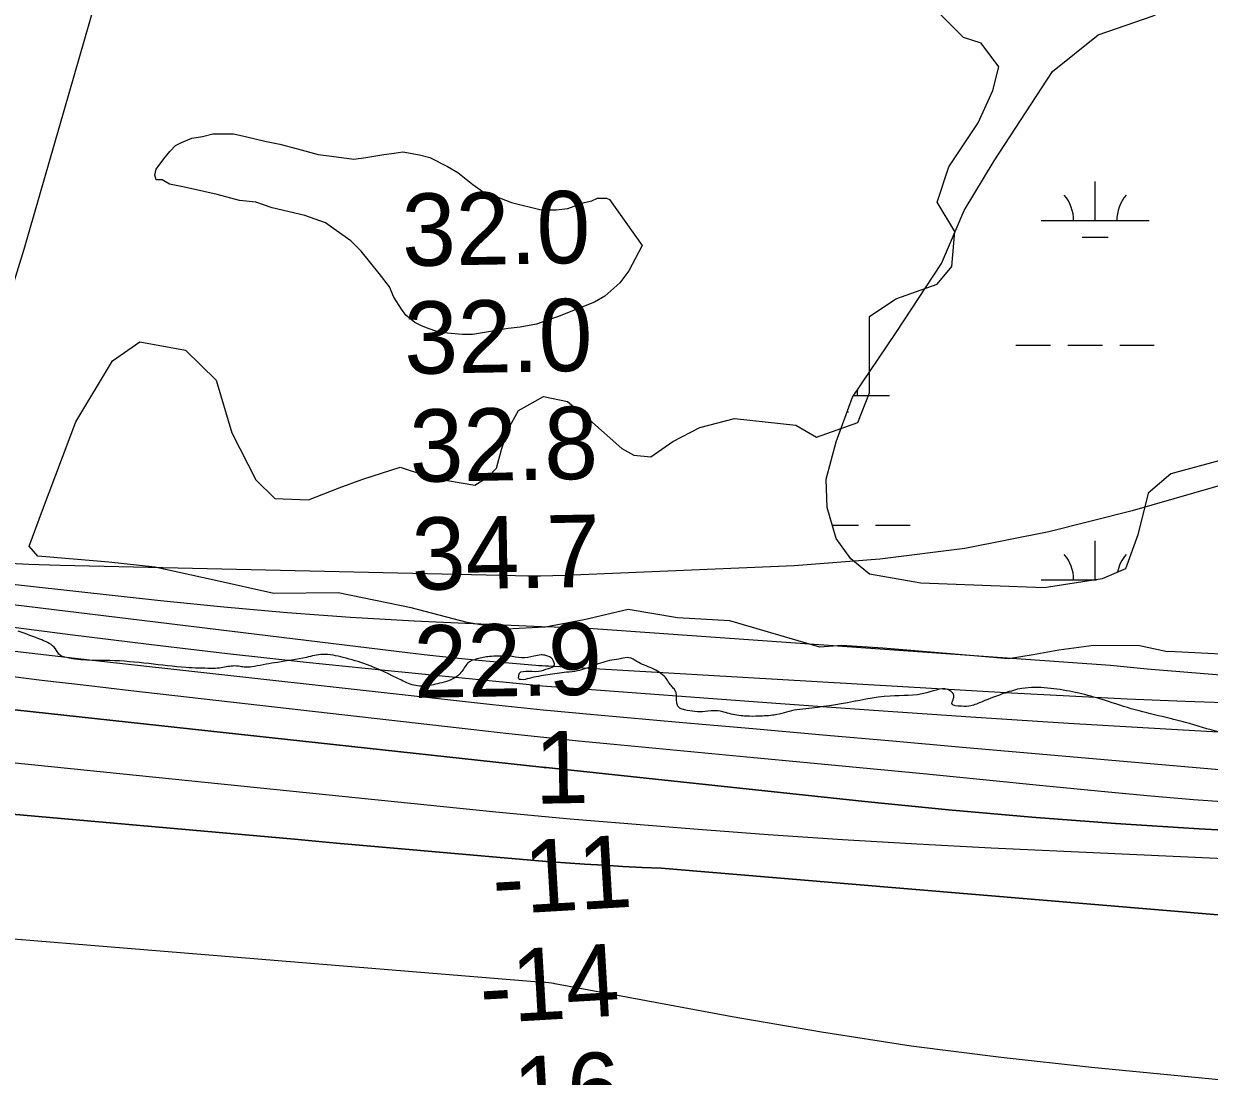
# Model space of a CAD drawing. Extents: x 3297772 to 3335630, y 634068 to 659439.
# Drawn here: x 3325224 to 3326321, y 647396 to 648371 of the extents above; entities that cross this region are included whole.
import ezdxf

# ---------------------------------------------------------------- set-up
doc = ezdxf.new("R2010")
doc.units = 0
for name, color, linetype in [('V-RIVR-EDGE', 7, 'Continuous'), ('V-RIVR-RANG', 7, 'Continuous'), ('V-SITE-VEGE', 7, 'Continuous'), ('V-TOPO-DPTH', 7, 'Continuous'), ('V-TOPO-MAJR', 7, 'Continuous'), ('V-TOPO-MINR', 7, 'Continuous'), ('V-TOPO-WATR', 7, 'Continuous'), ('V-WETL-SWMP', 7, 'Continuous')]:
    doc.layers.add(name, color=color, linetype=linetype)

msp = doc.modelspace()

# ---------------------------------------------------------------- linework, layer by layer
at = {"layer": 'V-RIVR-EDGE'}
for points in [[(3333439.4, 648130.1), (3333432.3, 648128.6), (3333393.5, 648121.3), (3333365.9, 648117.1), (3333332.2, 648114.9), (3333298.4, 648114.2), (3333260.8, 648112.7), (3333230.2, 648112), (3333195.3, 648109), (3333136.3, 648103), (3333088.6, 648097.7), (3333047.1, 648092.7), (3333001.7, 648085.1), (3332967.9, 648078.9), (3332933.4, 648077.1), (3332910.9, 648076), (3332895, 648074.5), (3332874.5, 648073.4), (3332860.9, 648070.3), (3332849.2, 648064.9), (3332842.2, 648063), (3332807, 648061.9), (3332785.2, 648058.1), (3332742.9, 648051.2), (3332702.2, 648046.3), (3332606, 648034.5), (3332570.7, 648028.4), (3332514.8, 648018.8), (3332458.6, 648008.9), (3332396.1, 648000.5), (3332317.7, 647987.9), (3332285.5, 647982.5), (3332246.4, 647976.4), (3332208, 647971.9), (3332152.9, 647965.8), (3332088.5, 647961.3), (3332048.9, 647954.8), (3332019, 647950.2), (3331983.4, 647943.3), (3331945.3, 647935.7), (3331898, 647927.6), (3331843.3, 647918.1), (3331789, 647907.7), (3331738.2, 647900.5), (3331714.1, 647898.6), (3331693.9, 647894), (3331644.7, 647886.8), (3331609.4, 647880.3), (3331580.3, 647876.1), (3331563.2, 647876.1), (3331548.1, 647876.5), (3331538.4, 647876.2), (3331524.8, 647873.9), (3331503.5, 647868.5), (3331463.9, 647860.5), (3331403, 647851.3), (3331393.3, 647846.7), (3331382, 647841.3), (3331348.6, 647836.3), (3331302.5, 647830.2), (3331254.8, 647825.7), (3331162.1, 647821.6), (3331119, 647820.6), (3331084.5, 647817.2), (3331048, 647811.1), (3330992.9, 647804.6), (3330947.6, 647800.1), (3330916.9, 647796.7), (3330882, 647795.2), (3330846.7, 647791.4), (3330781.9, 647785.7), (3330745.1, 647780), (3330721.8, 647780.1), (3330687.3, 647783.7), (3330659, 647784.9), (3330629.5, 647784.6), (3330565.1, 647780.1), (3330512.8, 647775.2), (3330464.3, 647771.4), (3330411.1, 647764.9), (3330328.9, 647756.6), (3330280.8, 647752.5), (3330223, 647743.7), (3330159.8, 647733.8), (3330098.9, 647726.2), (3330018.6, 647717.1), (3329963.9, 647709.4), (3329917.7, 647703), (3329903.4, 647702.2), (3329890.6, 647702.2), (3329873.5, 647706.9), (3329862.3, 647707.7), (3329851.8, 647705.8), (3329827.7, 647698.9), (3329814.5, 647697.4), (3329809.5, 647696.6), (3329807.9, 647698.6), (3329806.8, 647701.7), (3329801.8, 647702.1), (3329782.7, 647701.3), (3329745.5, 647698.7), (3329718.7, 647695.7), (3329678, 647692.7), (3329648.1, 647688.9), (3329602, 647682), (3329556.2, 647675.9), (3329520.9, 647674.5), (3329508.1, 647675.3), (3329497.3, 647678.4), (3329465.5, 647674.6), (3329435.2, 647672.7), (3329406.1, 647671.3), (3329386.7, 647673.2), (3329372, 647678.7), (3329360.8, 647680.7), (3329347.6, 647681.5), (3329329.4, 647681.1), (3329318.9, 647676.5), (3329310, 647675.4), (3329285.5, 647674.7), (3329264.2, 647671.2), (3329230, 647669), (3329205.6, 647671), (3329192.8, 647669.5), (3329173.8, 647668.3), (3329159.9, 647669.5), (3329154.8, 647672.7), (3329142, 647670), (3329119.5, 647667.3), (3329104.4, 647666.2), (3329092.4, 647665.1), (3329070.3, 647665.1), (3329052.4, 647664.4), (3329042.7, 647664.8), (3329037.3, 647667.1), (3329035.4, 647670.6), (3329031.1, 647673), (3329023.4, 647673.4), (3329005.9, 647675.3), (3328975.7, 647679.3), (3328944.7, 647682.1), (3328895.4, 647682.6), (3328867.5, 647686.5), (3328838.8, 647688.6), (3328809.3, 647690.2), (3328773.7, 647691.8), (3328729.1, 647689.6), (3328666.2, 647693.6), (3328624.8, 647694.9), (3328580.2, 647695.8), (3328546.8, 647693.5), (3328506.8, 647687.1), (3328492.9, 647683.2), (3328482.8, 647675.1), (3328471.9, 647673.2), (3328434.3, 647669.8), (3328399.4, 647666.8), (3328372.6, 647660.6), (3328345.8, 647656.4), (3328313.2, 647653.4), (3328276, 647651.6), (3328220.2, 647646.3), (3328210.4, 647641.6), (3328198, 647638.2), (3328173.6, 647636.7), (3328112.7, 647631.8), (3328044, 647626.5), (3328041.3, 647628.5), (3328031.7, 647644), (3328021.2, 647654.5), (3328011.2, 647660.4), (3327998, 647665.8), (3327984.4, 647669), (3327951.1, 647672.1), (3327903.4, 647675), (3327857.3, 647678.6), (3327817.7, 647677.9), (3327782.8, 647676.4), (3327750.6, 647676.1), (3327707.9, 647675.5), (3327667.6, 647675.6), (3327640.5, 647680.3), (3327623.8, 647683), (3327599.4, 647684.3), (3327563.3, 647682), (3327529.2, 647680.2), (3327489.2, 647675.2), (3327442.7, 647667.6), (3327414.7, 647665.7), (3327389.5, 647666.2), (3327373.6, 647665.4), (3327367.4, 647667.4), (3327351.5, 647674.4), (3327334.1, 647680.3), (3327331.8, 647683.8), (3327330.3, 647688.8), (3327320.6, 647691.9), (3327317.5, 647695.8), (3327317.9, 647700.9), (3327315.2, 647702.8), (3327303.2, 647707.1), (3327298.5, 647707.5), (3327292.3, 647704.8), (3327281.8, 647701.7), (3327271.7, 647701.7), (3327235.3, 647702.2), (3327199.2, 647703.5), (3327169, 647704.3), (3327108.9, 647708.3), (3327072.8, 647712.7), (3327031.7, 647717.5), (3326986.7, 647719.9), (3326955.3, 647719.2), (3326928.9, 647718.1), (3326908, 647716.2), (3326887.8, 647708.1), (3326876.2, 647702.7), (3326868.8, 647702), (3326856.8, 647704.7), (3326842, 647704.7), (3326809.5, 647703.3), (3326777.3, 647698.3), (3326760.2, 647695.6), (3326748.9, 647691.4), (3326738.1, 647689.5), (3326737.3, 647691), (3326736.9, 647694.9), (3326734.6, 647696.9), (3326712.9, 647700.4), (3326678.4, 647702), (3326660.2, 647703.6), (3326628.4, 647711.5), (3326607.8, 647715.4), (3326582.6, 647714.3), (3326557, 647710.1), (3326535.7, 647709), (3326505.8, 647710.2), (3326476, 647711.9), (3326436.8, 647712.7), (3326394.5, 647711.7), (3326361.6, 647711.7), (3326334.8, 647714.1), (3326302.7, 647722.8), (3326245.3, 647737.6), (3326217, 647746.6), (3326194.5, 647752.1), (3326171.3, 647755.7), (3326147.6, 647755.3), (3326132.1, 647751.1), (3326110.7, 647743), (3326100.3, 647739.2), (3326091.7, 647738.8), (3326082.8, 647741.5), (3326084.4, 647746.2), (3326084.4, 647749.7), (3326081.3, 647753.2), (3326059.6, 647751.3), (3326025.8, 647748.3), (3325980.4, 647741), (3325936.6, 647735.3)], [(3325936.6, 647735.3), (3325918.4, 647730.7), (3325904, 647729.6), (3325892.8, 647729.6), (3325878.4, 647731.6), (3325864.9, 647734.7), (3325854.4, 647733.9), (3325835.4, 647735.5), (3325831.1, 647737.1), (3325828.8, 647739.8), (3325828, 647743.7), (3325826.5, 647753.8), (3325823.8, 647756.9), (3325817.6, 647765.4), (3325805.2, 647774), (3325791.3, 647780.2), (3325783.9, 647783.8), (3325776.9, 647783), (3325768, 647781.5), (3325751.3, 647776.5), (3325736.2, 647771.5), (3325726.1, 647770.3), (3325708.7, 647768), (3325691.6, 647764.6), (3325683.8, 647763.5), (3325681.9, 647764.2), (3325681.9, 647766.6), (3325681.9, 647767.7), (3325700.1, 647771.2), (3325709.4, 647773.9), (3325714.9, 647776.9), (3325714.5, 647779.7), (3325713, 647782.4), (3325707.1, 647785.9), (3325702.5, 647786.3), (3325695.9, 647785.1), (3325684.6, 647783.6), (3325673, 647785.2), (3325662.9, 647785.2), (3325654.8, 647784.9), (3325643.2, 647782.6), (3325634.6, 647778.7), (3325631.5, 647774.4), (3325624.5, 647766.3), (3325608.6, 647760.1), (3325593.8, 647757.5), (3325586.5, 647757.9), (3325573.3, 647762.9), (3325541.1, 647777.4), (3325519.4, 647784), (3325500.5, 647786.8), (3325485.3, 647784.1), (3325458.6, 647779.5), (3325437.2, 647775.7), (3325429.1, 647774.9), (3325424, 647775.7), (3325417.4, 647776.1), (3325405, 647774.2), (3325396.9, 647773.9), (3325374, 647774.7), (3325339.5, 647778.3), (3325303.4, 647781.1), (3325260.4, 647784.7), (3325257.7, 647785.8), (3325253, 647792), (3325240.3, 647800.2), (3325218.6, 647808.4)]]:
    msp.add_spline(points, degree=3, dxfattribs=at)
at = {"layer": 'V-SITE-VEGE'}
for points in [[(3325326.3, 648517.3), (3325223.7, 648161.8), (3325142.4, 647899.2), (3325139.3, 647891.3), (3325126.8, 647883.4), (3325085.9, 647889.4), (3324990.2, 647891.8), (3324842.5, 647908), (3324762.4, 647920), (3324715.2, 647935.4), (3324671.2, 647950.8), (3324627.1, 647961.5), (3324584.7, 647969), (3324501.5, 647979.4), (3324405.8, 647970.9), (3324357.1, 647970.5), (3324299, 647982.7), (3324218.8, 648005.7)], [(3325804.2, 647969.8), (3325824.5, 647984), (3325849.5, 647996.8), (3325881.6, 648005.4), (3325938.5, 647999), (3325957.6, 647988.1), (3325995.6, 648001.7), (3326006.5, 648028.9), (3326006.5, 648056.1), (3326006.5, 648099.6), (3326031, 648116), (3326069.1, 648129.6), (3326082.7, 648145.9), (3326085.4, 648178.5), (3326069.1, 648205.7), (3326079.9, 648238.4), (3326107.1, 648279.2), (3326120.7, 648309.1), (3326126.2, 648330.9), (3326109.9, 648352.7), (3326093.5, 648358.1), (3326063.6, 648388)], [(3326331.8, 647787), (3326283.6, 647789.4), (3326282.3, 647789.1), (3326256.3, 647794.9), (3326214.2, 647795), (3326181.7, 647790.7), (3326158.1, 647786.5), (3326135.2, 647782.7), (3326085.3, 647787), (3326018.8, 647792.5), (3325980.9, 647795.2), (3325960.7, 647793.5), (3325877.4, 647818), (3325828.8, 647820.8), (3325783.2, 647828.4), (3325742.5, 647818.7), (3325706.4, 647812.1), (3325670.3, 647810.3), (3325634.2, 647816.3), (3325582.3, 647830.1), (3325514.7, 647843.7), (3325455.1, 647843.3), (3325400.1, 647855.5), (3325345, 647867.6), (3325302.6, 647872.1), (3325269.7, 647875), (3325236.7, 647877.9), (3325228.8, 647887.2), (3325241.1, 647920.3), (3325271.9, 648002.1), (3325306, 648058.8), (3325331, 648076.3), (3325373.4, 648068.7), (3325401.9, 648040.7), (3325416.4, 647992.1), (3325438.6, 647948.4), (3325456, 647931.2), (3325487.4, 647929.9), (3325515.6, 647941), (3325537.5, 647949), (3325572, 647960.3), (3325595.6, 647952.6), (3325616, 647948), (3325641.1, 647943.5), (3325653.6, 647951.4), (3325661.4, 647959.3), (3325666, 647976.6), (3325672.2, 647995.5), (3325681.5, 648012.8), (3325704.9, 648025.6), (3325726.9, 648021), (3325747.4, 648003.9), (3325777.4, 647977.4), (3325788.5, 647971.2), (3325804.2, 647969.8)]]:
    msp.add_lwpolyline(points, dxfattribs=at)
msp.add_lwpolyline([(3325796.1, 648165.4), (3325783.7, 648142), (3325775.4, 648131), (3325761.7, 648118.6), (3325752, 648113.1), (3325717.6, 648099.4), (3325709.4, 648096.7), (3325698.4, 648092.6), (3325683.2, 648089.8), (3325672.2, 648088.5), (3325639.2, 648083), (3325629.6, 648083), (3325615.8, 648084.4), (3325606.2, 648085.8), (3325597.9, 648088.6), (3325591.1, 648091.3), (3325585.6, 648094.1), (3325577.3, 648101), (3325573.2, 648106.5), (3325566.3, 648117.5), (3325562.2, 648127.1), (3325552.6, 648139.5), (3325536.1, 648160.2), (3325526.5, 648169.8), (3325512.8, 648179.5), (3325503.1, 648186.3), (3325483.9, 648193.2), (3325453.6, 648200.2), (3325438.5, 648205.7), (3325423.4, 648207.1), (3325402.7, 648212.6), (3325390.4, 648215.4), (3325372.5, 648219.5), (3325358.7, 648222.3), (3325351.9, 648226.4), (3325346.4, 648226.4), (3325345, 648230.5), (3325346.4, 648236), (3325353.3, 648245.7), (3325358.8, 648252.5), (3325364.3, 648258), (3325369.8, 648260.8), (3325379.4, 648264.9), (3325389.1, 648266.3), (3325398.7, 648269), (3325417.9, 648269), (3325430.3, 648266.2), (3325446.8, 648262.1), (3325460.6, 648259.3), (3325477.1, 648255.1), (3325496.3, 648249.6), (3325508.7, 648248.2), (3325529.3, 648245.5), (3325540.3, 648246.8), (3325556.9, 648249.6), (3325566.5, 648250.9), (3325574.7, 648252.3), (3325589.9, 648249.5), (3325599.5, 648246.8), (3325616, 648238.5), (3325625.6, 648233), (3325639.4, 648221.9), (3325649, 648215.1), (3325664.1, 648209.5), (3325675.1, 648205.4), (3325702.6, 648198.5), (3325716.4, 648198.5), (3325727.4, 648199.8), (3325742.5, 648205.3), (3325749.4, 648206.7), (3325754.9, 648209.4), (3325763.1, 648209.4), (3325765.9, 648208)], close=True, dxfattribs=at)
at = {"layer": 'V-TOPO-DPTH'}
for points in [[(3326436.5, 647670.6), (3326092.6, 647700.7), (3326027.9, 647706.4), (3325963.2, 647712.1), (3325898.5, 647717.8), (3325833.8, 647723.5), (3325751.3, 647730.8), (3325727.9, 647733), (3325704.4, 647735.2), (3325681, 647737.7), (3325657.6, 647740.2), (3325284.5, 647781.5), (3325249.9, 647785.4), (3325215.3, 647789.5)], [(3325113, 647746.6), (3325703.2, 647682.5), (3325703.5, 647682.4), (3325705.5, 647682.2), (3325706.4, 647682.1), (3325707, 647682.1), (3325707.3, 647682), (3326002.3, 647650.6), (3326079.6, 647642.9), (3326156.8, 647636.1), (3326234.2, 647630.4), (3326311.6, 647625.4), (3326413.7, 647619.7)], [(3325113, 647746.6), (3325703.2, 647682.5), (3325703.5, 647682.4), (3325705.5, 647682.2), (3325706.4, 647682.1), (3325707, 647682.1), (3325707.3, 647682), (3326002.3, 647650.6), (3326079.6, 647642.9), (3326156.8, 647636.1), (3326234.2, 647630.4), (3326311.6, 647625.4), (3326413.7, 647619.7)], [(3325104.7, 647648.6), (3325474.4, 647615.7), (3325513.2, 647612.2), (3325552, 647608.7), (3325590.8, 647605.3), (3325629.6, 647601.9), (3325671.8, 647598.2), (3325689.6, 647596.6), (3325707.3, 647595.2), (3325725, 647593.9), (3325742.7, 647592.7), (3325760.5, 647591.6), (3325778.2, 647590.5), (3325796, 647589.6), (3325813.8, 647588.8), (3326506.2, 647530.9)], [(3326506.2, 647530.9), (3325813.8, 647588.8), (3325796, 647589.6), (3325778.2, 647590.5), (3325760.5, 647591.6), (3325742.7, 647592.7), (3325725, 647593.9), (3325707.3, 647595.2), (3325689.6, 647596.6), (3325671.8, 647598.2), (3325629.6, 647601.9), (3325590.8, 647605.3), (3325552, 647608.7), (3325513.2, 647612.2), (3325474.4, 647615.7), (3325104.7, 647648.6)]]:
    msp.add_lwpolyline(points, dxfattribs=at)
at = {"layer": 'V-TOPO-MAJR'}
msp.add_lwpolyline([(3326331.5, 647767.7), (3326297.5, 647770.4), (3326263.5, 647773.3), (3326229.5, 647776.6), (3325737.9, 647811.6), (3325702.8, 647812.5), (3325667.8, 647813.8), (3325632.7, 647815.4), (3325585.1, 647817.7), (3325526.3, 647821.1), (3325467.5, 647825.3), (3325408.9, 647830.5), (3325350.2, 647836.4), (3325106.5, 647863.2)], dxfattribs=at)
at = {"layer": 'V-TOPO-MINR'}
for points in [[(3326363.2, 647952.5), (3326249.8, 647919.7), (3326172.6, 647900.4), (3326094.8, 647884.8), (3326016, 647874.9), (3325936.7, 647868.8), (3325724.9, 647860), (3325713.4, 647859.6), (3325701.9, 647859.4), (3325690.3, 647859.4), (3325678.8, 647859.6), (3325257.4, 647869.2), (3325228.3, 647870.2), (3325199.1, 647871.7)], [(3326352.4, 647741.4), (3326298.8, 647743.3), (3326245.1, 647745.5), (3326191.5, 647748.1), (3326137.9, 647751), (3325709.5, 647775.8), (3325706.5, 647776), (3325703.6, 647776.2), (3325700.6, 647776.4), (3325697.6, 647776.6), (3325662, 647779.7), (3325641.2, 647781.6), (3325620.4, 647783.6), (3325599.7, 647785.9), (3325578.9, 647788.3), (3325122.2, 647843.8)], [(3326399.4, 647710.9), (3326280.9, 647717.7), (3326190.6, 647723), (3326100.4, 647728.7), (3326010.1, 647734.9), (3325919.9, 647741.3), (3325728.6, 647755.6), (3325716.3, 647756.5), (3325704, 647757.5), (3325691.7, 647758.6), (3325679.4, 647759.8), (3325558, 647771.8), (3325485.1, 647779.4), (3325412.2, 647787.4), (3325339.4, 647796), (3325266.7, 647805), (3325140.1, 647821.3)], [(3326436.5, 647670.6), (3326092.6, 647700.7), (3326027.9, 647706.4), (3325963.2, 647712.1), (3325898.5, 647717.8), (3325833.8, 647723.5), (3325751.3, 647730.8), (3325727.9, 647733), (3325704.4, 647735.2), (3325681, 647737.7), (3325657.6, 647740.2), (3325284.5, 647781.5), (3325249.9, 647785.4), (3325215.3, 647789.5)], [(3326346.1, 647649.4), (3326306.5, 647652.3), (3326266.9, 647655.6), (3326227.3, 647659.3), (3326166.9, 647665.3), (3326111.6, 647670.8), (3326056.2, 647676.2), (3326000.8, 647681.5), (3325945.4, 647686.7), (3325899.4, 647691), (3325867, 647694.1), (3325834.6, 647697.1), (3325802.2, 647700.2), (3325769.8, 647703.3), (3325737.3, 647706.5), (3325705, 647709.8), (3325672.6, 647713.3), (3325640.2, 647716.9), (3325322.8, 647753.2), (3325281.6, 647758), (3325240.3, 647762.8), (3325199.1, 647767.8)], [(3326422.5, 647593.6), (3326119.2, 647607.5), (3326050.3, 647611), (3325981.5, 647615), (3325912.7, 647619.8), (3325843.9, 647625), (3325752.3, 647632.4), (3325729.4, 647634.3), (3325706.4, 647636.4), (3325683.5, 647638.5), (3325660.7, 647640.8), (3325234.1, 647684.2), (3325206.6, 647687.1)], [(3326506.2, 647530.9), (3325813.8, 647588.8), (3325796, 647589.6), (3325778.2, 647590.5), (3325760.5, 647591.6), (3325742.7, 647592.7), (3325725, 647593.9), (3325707.3, 647595.2), (3325689.6, 647596.6), (3325671.8, 647598.2), (3325629.6, 647601.9), (3325590.8, 647605.3), (3325552, 647608.7), (3325513.2, 647612.2), (3325474.4, 647615.7), (3325104.7, 647648.6)], [(3326460.9, 647380.2), (3326211.9, 647404.3), (3326128.4, 647413.5), (3326045.2, 647424.1), (3325962.2, 647437), (3325879.5, 647451.3), (3325715.4, 647481.9), (3325714.3, 647482.1), (3325712.1, 647482.4), (3325709.8, 647482.7), (3325706.5, 647483), (3325703.5, 647483.2), (3325700.4, 647483.4), (3325112.2, 647531.6)]]:
    msp.add_lwpolyline(points, dxfattribs=at)
at = {"layer": 'V-TOPO-WATR'}
msp.add_lwpolyline([(3326413.7, 647619.7), (3326311.6, 647625.4), (3326234.2, 647630.4), (3326156.8, 647636.1), (3326079.6, 647642.9), (3326002.3, 647650.6), (3325707.3, 647682), (3325707, 647682.1), (3325706.4, 647682.1), (3325705.5, 647682.2), (3325703.5, 647682.4), (3325703.2, 647682.5), (3325113, 647746.6)], dxfattribs=at)
at = {"layer": 'V-WETL-SWMP'}
for p, q in [((3326215.5, 648188.6), (3326215.5, 648224.6)), ((3326165.5, 648188.6), (3326265.5, 648188.6)), ((3326203.5, 648173.1), (3326227.5, 648173.1)), ((3326142.1, 648073.1), (3326174.1, 648073.1)), ((3326190.1, 648073.1), (3326222.1, 648073.1)), ((3326238.1, 648073.1), (3326270.1, 648073.1)), ((3325992.1, 648026.7), (3326025, 648026.7)), ((3325985.9, 648011.3), (3325987, 648011.3)), ((3325972, 647906.6), (3325996.2, 647906.6)), ((3326012.2, 647906.6), (3326044.2, 647906.6)), ((3326215.5, 647855.9), (3326215.5, 647891.9)), ((3326165.5, 647855.9), (3326216.6, 647855.9))]:
    msp.add_line(p, q, dxfattribs=at)
msp.add_lwpolyline([(3326341.3, 647969.1), (3326285.3, 647953.9), (3326264.4, 647936.2), (3326254.9, 647897.5), (3326243.4, 647866.1), (3326221.9, 647856.7), (3326168.1, 647848.4), (3326054, 647852.7), (3326006.4, 647861.2), (3325989.2, 647875.3), (3325975.6, 647894.2), (3325967.3, 647922.9), (3325966.3, 647949.1), (3325975.7, 647983.6), (3325990.9, 648024.9), (3326031.3, 648085), (3326073.2, 648148.8), (3326094.2, 648197.9), (3326122, 648243.9), (3326175.9, 648326.5), (3326218.3, 648360.5), (3326269.1, 648378.2), (3326343.9, 648417.3)], dxfattribs=at)
for centre, start, end in [((3326160.2, 648189), 359.2282, 40.7718), ((3326270.7, 648189), 139.2282, 180.7718), ((3326030.3, 648027.2), 173.2302, 180.7718), ((3326160.2, 647856.4), 359.2282, 40.7718), ((3326270.7, 647856.4), 139.2282, 169.3002)]:
    msp.add_arc(centre, 35.2, start, end, dxfattribs=at)

# ---------------------------------------------------------------- texts
at = {"layer": 'V-RIVR-RANG'}
for s, rotation, p in [('32.0', 1.0283, (3325574.3, 648146.3)), ('32.0', 1.0283, (3325576.3, 648046.4)), ('32.8', 1.0283, (3325581.3, 647946.4)), ('34.7', 1.0283, (3325583.3, 647846.4)), ('22.9', 1.0283, (3325585.1, 647746.5)), ('1', 1.0283, (3325697.1, 647648.5)), ('-11', 3.3466, (3325658.9, 647545.7)), ('-14', 3.3466, (3325647.3, 647445)), ('-16', 3.3466, (3325649.1, 647345))]:
    msp.add_text(s, height=67, rotation=rotation, dxfattribs=at).set_placement(p)

doc.saveas('drawing.dxf')
